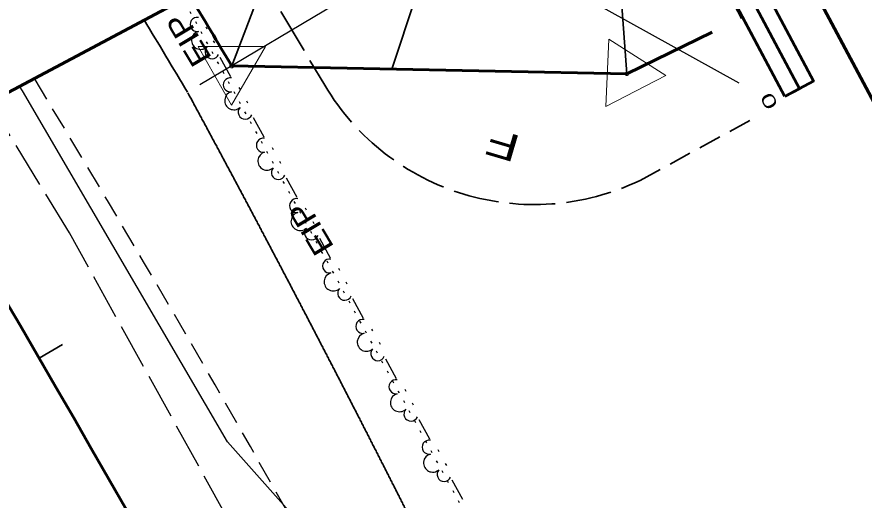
# Model space of a CAD drawing. Extents: x 2402199 to 2404507, y 568050 to 571478.
# Drawn here: x 2402420.4 to 2402576.7, y 571125.2 to 571214.3 of the extents above; entities that cross this region are included whole.
import ezdxf
from ezdxf.enums import TextEntityAlignment as Align

# ---------------------------------------------------------------- set-up
doc = ezdxf.new("R2010")
doc.units = 0
doc.header["$LTSCALE"] = 1.4
doc.header["$PDMODE"] = 32
doc.header["$PDSIZE"] = 0.7
for name, pattern in [('DOTTED', [1.5, 0.3, -1.2]), ('LONG_DASHED', [7.5, 6, -1.5]), ('MEDIUM_DASHED', [4.5, 3, -1.5])]:
    doc.linetypes.add(name, pattern=pattern)
for name, color, linetype, lineweight in [('1', 7, 'Continuous', 35), ('11', 7, 'Continuous', 25), ('15', 7, 'DOTTED', 40), ('17', 7, 'MEDIUM_DASHED', 35), ('19', 7, 'Continuous', 35), ('28', 7, 'Continuous', 25), ('3', 7, 'Continuous', 25), ('4', 7, 'Continuous', 13), ('52', 7, 'Continuous', 25), ('6', 7, 'Continuous', 35), ('62', 7, 'Continuous', 60), ('63', 7, 'Continuous', 35), ('9', 7, 'Continuous', 13)]:
    doc.layers.add(name, color=color, linetype=linetype, lineweight=lineweight)
doc.layers.add('14', color=7, linetype='Continuous')

msp = doc.modelspace()

# ---------------------------------------------------------------- linework, layer by layer
at = {"layer": '1'}
msp.add_arc((2399929.798, 569697.989), 2935.633, 30.78279, 31.08702, dxfattribs=at)
for points in [[(2402483.513, 571140.326), (2402483.095, 571141.14), (2402482.672, 571141.963), (2402482.255, 571142.777), (2402481.837, 571143.591), (2402481.418, 571144.405), (2402480.999, 571145.218), (2402480.581, 571146.032), (2402480.161, 571146.845), (2402479.742, 571147.659), (2402479.322, 571148.471), (2402478.902, 571149.285), (2402478.482, 571150.098), (2402478.056, 571150.92), (2402477.635, 571151.732), (2402477.215, 571152.544), (2402476.794, 571153.357), (2402476.372, 571154.169), (2402475.95, 571154.981), (2402475.528, 571155.794), (2402475.106, 571156.606), (2402474.683, 571157.417), (2402474.26, 571158.229), (2402473.837, 571159.041), (2402473.413, 571159.853), (2402472.985, 571160.673), (2402472.561, 571161.484), (2402472.137, 571162.295), (2402471.713, 571163.106), (2402471.288, 571163.917), (2402470.863, 571164.728), (2402470.438, 571165.539), (2402470.012, 571166.349), (2402469.587, 571167.159), (2402469.161, 571167.97), (2402468.735, 571168.78), (2402468.303, 571169.599), (2402467.876, 571170.409), (2402467.45, 571171.218), (2402467.022, 571172.028), (2402466.595, 571172.837), (2402466.167, 571173.647), (2402465.739, 571174.456), (2402465.311, 571175.265), (2402464.882, 571176.074), (2402464.453, 571176.883), (2402464.024, 571177.693), (2402463.59, 571178.51), (2402463.16, 571179.318), (2402462.731, 571180.126), (2402462.3, 571180.935), (2402461.87, 571181.743), (2402461.439, 571182.551), (2402461.009, 571183.358), (2402460.578, 571184.167), (2402460.146, 571184.974), (2402459.714, 571185.782), (2402459.282, 571186.59), (2402458.845, 571187.405), (2402458.413, 571188.213), (2402457.98, 571189.02), (2402457.547, 571189.826), (2402457.114, 571190.633), (2402456.681, 571191.44), (2402456.247, 571192.247), (2402455.813, 571193.053), (2402455.379, 571193.859), (2402454.945, 571194.666), (2402454.509, 571195.472), (2402454.07, 571196.286), (2402453.635, 571197.092), (2402453.199, 571197.897), (2402452.763, 571198.703), (2402451.891, 571200.313)], [(2402513.706, 571079.688), (2402513.308, 571080.51), (2402512.909, 571081.333), (2402512.511, 571082.156), (2402512.112, 571082.978), (2402511.713, 571083.801), (2402511.314, 571084.623), (2402510.914, 571085.446), (2402510.514, 571086.268), (2402510.113, 571087.091), (2402509.708, 571087.921), (2402509.308, 571088.743), (2402508.907, 571089.564), (2402508.505, 571090.386), (2402508.104, 571091.207), (2402507.703, 571092.029), (2402507.3, 571092.85), (2402506.898, 571093.671), (2402506.496, 571094.492), (2402506.093, 571095.313), (2402505.689, 571096.134), (2402505.281, 571096.964), (2402504.878, 571097.784), (2402504.474, 571098.604), (2402504.07, 571099.424), (2402503.666, 571100.245), (2402503.261, 571101.064), (2402502.856, 571101.884), (2402502.451, 571102.704), (2402502.046, 571103.524), (2402501.64, 571104.344), (2402501.234, 571105.164), (2402500.823, 571105.992), (2402500.416, 571106.811), (2402500.01, 571107.63), (2402499.603, 571108.449), (2402499.195, 571109.268), (2402498.788, 571110.086), (2402498.38, 571110.905), (2402497.972, 571111.724), (2402497.564, 571112.542), (2402497.155, 571113.361), (2402496.746, 571114.179), (2402496.333, 571115.006), (2402495.924, 571115.824), (2402495.514, 571116.642), (2402495.104, 571117.459), (2402494.694, 571118.277), (2402494.284, 571119.094), (2402493.873, 571119.912), (2402493.462, 571120.729), (2402493.051, 571121.547), (2402492.64, 571122.363), (2402492.228, 571123.181), (2402491.811, 571124.006), (2402491.399, 571124.823), (2402490.986, 571125.639), (2402490.574, 571126.456), (2402490.161, 571127.272), (2402489.748, 571128.088), (2402489.334, 571128.904), (2402488.92, 571129.72), (2402488.506, 571130.536), (2402488.092, 571131.351), (2402487.677, 571132.167), (2402487.257, 571132.992), (2402486.842, 571133.807), (2402486.427, 571134.622), (2402486.012, 571135.437), (2402485.596, 571136.252), (2402485.18, 571137.067), (2402484.763, 571137.882), (2402484.347, 571138.696), (2402483.93, 571139.511), (2402483.513, 571140.325)], [(2402513.706, 571079.688), (2402513.308, 571080.51), (2402512.909, 571081.333), (2402512.511, 571082.156), (2402512.112, 571082.978), (2402511.713, 571083.801), (2402511.314, 571084.623), (2402510.914, 571085.446), (2402510.514, 571086.268), (2402510.113, 571087.091), (2402509.708, 571087.921), (2402509.308, 571088.743), (2402508.907, 571089.564), (2402508.505, 571090.386), (2402508.104, 571091.207), (2402507.703, 571092.029), (2402507.3, 571092.85), (2402506.898, 571093.671), (2402506.496, 571094.492), (2402506.093, 571095.313), (2402505.689, 571096.134), (2402505.281, 571096.964), (2402504.878, 571097.784), (2402504.474, 571098.604), (2402504.07, 571099.424), (2402503.666, 571100.245), (2402503.261, 571101.064), (2402502.856, 571101.884), (2402502.451, 571102.704), (2402502.046, 571103.524), (2402501.64, 571104.344), (2402501.234, 571105.164), (2402500.823, 571105.992), (2402500.416, 571106.811), (2402500.01, 571107.63), (2402499.603, 571108.449), (2402499.195, 571109.268), (2402498.788, 571110.086), (2402498.38, 571110.905), (2402497.972, 571111.724), (2402497.564, 571112.542), (2402497.155, 571113.361), (2402496.746, 571114.179), (2402496.333, 571115.006), (2402495.924, 571115.824), (2402495.514, 571116.642), (2402495.104, 571117.459), (2402494.694, 571118.277), (2402494.284, 571119.094), (2402493.873, 571119.912), (2402493.462, 571120.729), (2402493.051, 571121.547), (2402492.64, 571122.363), (2402492.228, 571123.181), (2402491.811, 571124.006), (2402491.399, 571124.823), (2402490.986, 571125.639), (2402490.574, 571126.456), (2402490.161, 571127.272), (2402489.748, 571128.088), (2402489.334, 571128.904), (2402488.92, 571129.72), (2402488.506, 571130.536), (2402488.092, 571131.351), (2402487.677, 571132.167), (2402487.257, 571132.992), (2402486.842, 571133.807), (2402486.427, 571134.622), (2402486.012, 571135.437), (2402485.596, 571136.252), (2402485.18, 571137.067), (2402484.763, 571137.882), (2402484.347, 571138.696), (2402483.93, 571139.511), (2402483.513, 571140.325)]]:
    msp.add_spline(points, degree=3, dxfattribs=at)
at = {"layer": '11', "linetype": 'DOTTED'}
msp.add_line((2402506.107, 571117.3), (2402451.036, 571217.605), dxfattribs=at)
at = {"layer": '11'}
for p, q in [((2402455.475, 571212.078), (2402455.277, 571212.438)), ((2402456.856, 571209.56), (2402456.66, 571209.919)), ((2402459.853, 571203.252), (2402457.879, 571206.847)), ((2402461.593, 571200.932), (2402461.396, 571201.292)), ((2402462.975, 571198.418), (2402462.777, 571198.777)), ((2402465.971, 571192.108), (2402463.997, 571195.703)), ((2402467.712, 571189.789), (2402467.514, 571190.149)), ((2402469.094, 571187.273), (2402468.896, 571187.633)), ((2402472.089, 571180.964), (2402470.116, 571184.559)), ((2402473.831, 571178.645), (2402473.633, 571179.005)), ((2402475.213, 571176.127), (2402475.016, 571176.487)), ((2402478.208, 571169.821), (2402476.235, 571173.414)), ((2402479.949, 571167.501), (2402479.752, 571167.86)), ((2402481.33, 571164.986), (2402481.132, 571165.345)), ((2402484.327, 571158.676), (2402482.353, 571162.271)), ((2402486.067, 571156.358), (2402485.869, 571156.718)), ((2402487.448, 571153.842), (2402487.251, 571154.201)), ((2402490.445, 571147.532), (2402488.471, 571151.127)), ((2402492.185, 571145.214), (2402491.988, 571145.574)), ((2402493.567, 571142.696), (2402493.371, 571143.056)), ((2402496.564, 571136.388), (2402494.59, 571139.983)), ((2402498.304, 571134.068), (2402498.107, 571134.427)), ((2402499.685, 571131.554), (2402499.488, 571131.913)), ((2402502.682, 571125.244), (2402500.708, 571128.839))]:
    msp.add_line(p, q, dxfattribs=at)
for centre, radius, start, end in [((2402453.607, 571212.923), 1.297, 79.53681, 280.33338), ((2402454.27, 571210.012), 1.691, 104.73209, 312.80458), ((2402456.37, 571207.891), 1.297, 137.20328, 337.99985), ((2402459.725, 571201.779), 1.297, 79.53681, 280.33338), ((2402460.388, 571198.868), 1.691, 104.73209, 312.80458), ((2402462.489, 571196.746), 1.297, 137.20328, 337.99985), ((2402465.844, 571190.635), 1.297, 79.53681, 280.33338), ((2402466.507, 571187.724), 1.691, 104.73209, 312.80458), ((2402468.607, 571185.602), 1.297, 137.20328, 337.99985), ((2402471.962, 571179.491), 1.297, 79.53681, 280.33338), ((2402472.625, 571176.58), 1.691, 104.73209, 312.80458), ((2402474.726, 571174.458), 1.297, 137.20328, 337.99985), ((2402478.081, 571168.347), 1.297, 79.53681, 280.33338), ((2402478.744, 571165.436), 1.691, 104.73209, 312.80458), ((2402480.844, 571163.314), 1.297, 137.20328, 337.99985), ((2402484.199, 571157.203), 1.297, 79.53681, 280.33338), ((2402484.862, 571154.292), 1.691, 104.73209, 312.80458), ((2402486.963, 571152.17), 1.297, 137.20328, 337.99985), ((2402490.318, 571146.059), 1.297, 79.53681, 280.33338), ((2402490.981, 571143.148), 1.691, 104.73209, 312.80458), ((2402493.081, 571141.026), 1.297, 137.20328, 337.99985), ((2402496.436, 571134.915), 1.297, 79.53681, 280.33338), ((2402497.099, 571132.004), 1.691, 104.73209, 312.80458), ((2402499.2, 571129.882), 1.297, 137.20328, 337.99985)]:
    msp.add_arc(centre, radius, start, end, dxfattribs=at)
at = {"layer": '15'}
msp.add_arc((2399911.332, 569690.208), 2887.133, 22.84472, 37.57762, dxfattribs=at)
at = {"layer": '17', "linetype": 'LONG_DASHED'}
msp.add_line((2402463.715, 571224.347), (2402477.172, 571201.701), dxfattribs=at)
at = {"layer": '17', "linetype": 'Continuous', "lineweight": 60}
for p, q in [((2402548.672, 571211.487), (2402532.935, 571203.827)), ((2402532.935, 571203.827), (2402460.002, 571205.264))]:
    msp.add_line(p, q, dxfattribs=at)
at = {"layer": '17'}
msp.add_line((2402535.371, 571184.14), (2402556.949, 571195.919), dxfattribs=at)
at = {"layer": '17', "linetype": 'Continuous', "lineweight": 60}
msp.add_arc((2399929.798, 569697.989), 2945.133, 30.78279, 31.07706, dxfattribs=at)
at = {"layer": '17', "lineweight": 25}
msp.add_arc((2399953.615, 569708.021), 2887.133, 22.84472, 31.18511, dxfattribs=at)
at = {"layer": '17', "linetype": 'LONG_DASHED'}
msp.add_arc((2402515.857, 571224.689), 45, 210.71926, 295.69882, dxfattribs=at)
at = {"layer": '19'}
for p, q in [((2402532.935, 571203.827), (2402529.783, 571247.012)), ((2402460.002, 571205.264), (2402468.245, 571226.755))]:
    msp.add_line(p, q, dxfattribs=at)
at = {"layer": '19', "linetype": 'LONG_DASHED', "lineweight": 25}
msp.add_lwpolyline([(2402553.96, 570938.781), (2402489.547, 571067.152), (2402430.056, 571174.439), (2402385.495, 571247.202)], dxfattribs=at)
at = {"layer": '28'}
msp.add_lwpolyline([(2402608.658, 571102.353), (2402586.696, 571091.641), (2402563.737, 571084.481), (2402534.511, 571079.781), (2402500.05, 571089.933), (2402459.199, 571135.878), (2402421.36, 571200.686), (2402420.824, 571201.541)], dxfattribs=at)
at = {"layer": '3'}
msp.add_lwpolyline([(2402603.164, 571099.846), (2402586.696, 571091.641), (2402563.737, 571084.481), (2402534.511, 571079.781), (2402500.05, 571089.933), (2402459.199, 571135.878), (2402421.36, 571200.686), (2402420.824, 571201.541)], dxfattribs=at)
at = {"layer": '4', "lineweight": 35}
msp.add_line((2402542.396, 571236.363), (2402554.121, 571214.041), dxfattribs=at)
at = {"layer": '52'}
msp.add_line((2402553.666, 571202.093), (2402489.124, 571237.857), dxfattribs=at)
at = {"layer": '6'}
for p, q in [((2402489.56, 571204.682), (2402502.996, 571245.233)), ((2402424.462, 571151.326), (2402428.783, 571153.843))]:
    msp.add_line(p, q, dxfattribs=at)
at = {"layer": '62'}
msp.add_arc((2399929.798, 569697.989), 2887.133, 22.84477, 31.13893, dxfattribs=at)
at = {"layer": '63', "lineweight": 60}
msp.add_line((2402531.138, 571287.671), (2402757.403, 570862.128), dxfattribs=at)
at = {"layer": '63', "lineweight": 25}
msp.add_line((2402529.855, 571246.876), (2402454.128, 571201.765), dxfattribs=at)
at = {"layer": '63', "lineweight": 60}
msp.add_lwpolyline([(2402542.527, 571266.252), (2402277.643, 571125.41), (2402266.253, 571146.83), (2402531.138, 571287.671)], close=True, dxfattribs=at)
at = {"layer": '63', "lineweight": 53}
for points in [[(2402562.117, 571199.632), (2402533.948, 571252.609), (2402539.222, 571255.413), (2402567.39, 571202.436)], [(2402562.117, 571199.632), (2402548.081, 571226.03), (2402550.746, 571227.448), (2402564.783, 571201.049)]]:
    msp.add_lwpolyline(points, close=True, dxfattribs=at)
at = {"layer": '9'}
for points in [[(2402540.138, 571203.476), (2402529.041, 571197.768), (2402529.621, 571210.233)], [(2402459.971, 571198.052), (2402453.776, 571208.884), (2402466.254, 571208.859)]]:
    msp.add_lwpolyline(points, close=True, dxfattribs=at)
for p in [(2402460, 571205.265), (2402532.933, 571203.825)]:
    msp.add_point(p, dxfattribs=at)

# ---------------------------------------------------------------- texts
at = {"layer": '14', "width": 1.2}
for p in [(2402453.773, 571211.146), (2402476.342, 571176.297)]:
    msp.add_text('EIP', height=4, rotation=120.856, dxfattribs=at).set_placement(p, align=Align.CENTER)
at = {"layer": '17', "width": 1.45}
msp.add_text('F', height=5, rotation=163.601, dxfattribs=at).set_placement((2402510.749, 571193.054), align=Align.CENTER)
at = {"layer": '63', "width": 1.65}
msp.add_text('0', height=2.399, rotation=118, dxfattribs=at).set_placement((2402560.242, 571199.351), align=Align.CENTER)

doc.saveas('drawing.dxf')
